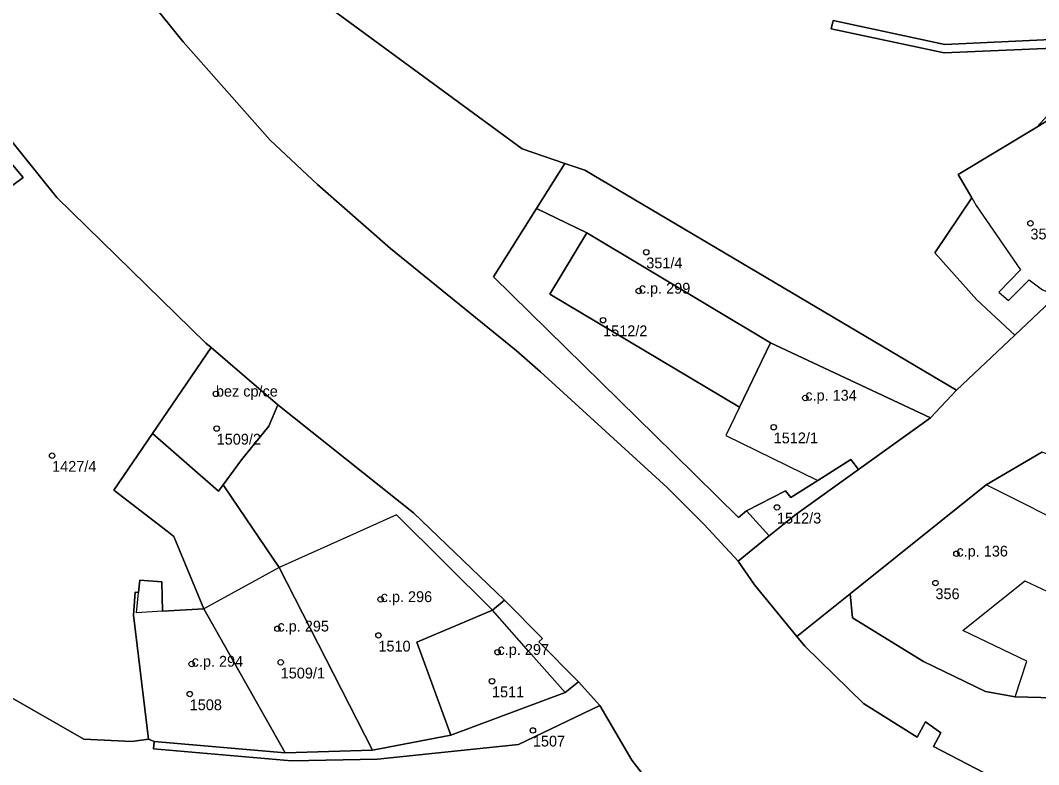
# Model space of a CAD drawing. Extents: x -878211 to -870363, y -1058464 to -1052522.
# Drawn here: x -874764.7 to -874670.5, y -1056238.3 to -1056169.5 of the extents above; entities that cross this region are included whole.
import ezdxf

# ---------------------------------------------------------------- set-up
doc = ezdxf.new("R2010")
doc.units = 0
for name, color, linetype in [('Definiční body', 7, 'Continuous'), ('Polygon budovy', 7, 'Continuous'), ('Polygon parcely', 7, 'Continuous')]:
    doc.layers.add(name, color=color, linetype=linetype)

msp = doc.modelspace()

# ---------------------------------------------------------------- linework, layer by layer
at = {"layer": 'Definiční body'}
for centre in [(-874671.3, -1056188.27994), (-874706.81, -1056190.94994), (-874707.5, -1056194.52994), (-874710.8, -1056197.22994), (-874746.59, -1056204.03994), (-874692.11, -1056204.41994), (-874746.52, -1056207.23994), (-874695.03, -1056207.11994), (-874761.73, -1056209.74994), (-874694.73, -1056214.52994), (-874678.14, -1056218.81994), (-874680.08, -1056221.51994), (-874731.36, -1056223.02994), (-874740.9, -1056225.74994), (-874731.57, -1056226.35994), (-874720.56, -1056227.90994), (-874748.83, -1056228.99994), (-874740.6, -1056228.84994), (-874721.07, -1056230.58994), (-874749.01, -1056231.77994), (-874717.29, -1056235.13994)]:
    msp.add_circle(centre, 0.25, dxfattribs=at)
at = {"layer": 'Polygon budovy'}
for points in [[(-874677.98, -1056183.76), (-874676.72, -1056185.93), (-874676.32, -1056186.62), (-874672.23, -1056192.57), (-874674.22, -1056194.63), (-874673.33, -1056195.4), (-874671.43, -1056193.49), (-874670.18, -1056194.41), (-874668.85, -1056194.96), (-874667.89, -1056195.41), (-874666.98, -1056194.26), (-874667.6, -1056193.93), (-874661.14, -1056188.51), (-874667.82, -1056178.48), (-874668.25, -1056177.84), (-874670.71, -1056179.4)], [(-874712.31, -1056189.17), (-874715.72, -1056194.83), (-874698.19, -1056205.27), (-874695.34, -1056199.31)], [(-874752.45, -1056207.7), (-874746.34, -1056213.03), (-874745.91, -1056212.45), (-874744.24, -1056210.15), (-874741.71, -1056207.02), (-874740.87, -1056205.06), (-874747.04, -1056199.75)], [(-874699.45, -1056207.9), (-874690.94, -1056212.04), (-874687.9, -1056210.09), (-874687.2, -1056211.04), (-874680.55, -1056206.24), (-874695.34, -1056199.31), (-874698.19, -1056205.27)], [(-874675.38, -1056212.44), (-874687.96, -1056222.51), (-874687.74, -1056224.74), (-874681.17, -1056228.78), (-874675.44, -1056231.54), (-874672.71, -1056232.05), (-874671.64, -1056228.75), (-874677.55, -1056225.92), (-874671.81, -1056221.33), (-874669.72, -1056222.29), (-874666.44, -1056216.93)], [(-874728.01, -1056226.99), (-874721.01, -1056224.03), (-874729.9, -1056215.22), (-874734.21, -1056217.16), (-874740.73, -1056220.09), (-874732.13, -1056236.97), (-874724.86, -1056235.58)], [(-874747.71, -1056223.89), (-874740.2, -1056237.21), (-874732.13, -1056236.97), (-874740.73, -1056220.09)], [(-874754.04, -1056222.36), (-874754.2, -1056224.49), (-874752.81, -1056235.95), (-874752.29, -1056236.15), (-874740.2, -1056237.21), (-874747.71, -1056223.89), (-874751.53, -1056224.13), (-874753.92, -1056224.28), (-874753.74, -1056222.39)], [(-874721.01, -1056224.03), (-874728.01, -1056226.99), (-874724.86, -1056235.58), (-874714.32, -1056231.63), (-874717.67, -1056227.86)]]:
    msp.add_lwpolyline(points, close=True, dxfattribs=at)
at = {"layer": 'Polygon parcely'}
for points in [[(-874779.01, -1056127.66), (-874780.45, -1056125.66), (-874793.17, -1056142.82), (-874792.46, -1056145.61), (-874788.37, -1056151.02), (-874786.78, -1056152.78), (-874770.12, -1056174.96), (-874761.29, -1056185.88), (-874747.51, -1056199.34), (-874747.04, -1056199.75), (-874740.87, -1056205.06), (-874728.32, -1056215.02), (-874719.92, -1056223.09), (-874716.4, -1056226.65), (-874716.73, -1056226.96), (-874713.06, -1056230.64), (-874711.1, -1056232.84), (-874708.16, -1056237.89), (-874707.28, -1056238.99), (-874703.07, -1056243.11), (-874695.31, -1056252.07), (-874686.26, -1056258.1), (-874668.18, -1056265.93)], [(-874755.19, -1056164.59), (-874749.63, -1056171.52), (-874741.58, -1056180.59), (-874737.21, -1056184.7), (-874730.46, -1056190.6), (-874718.85, -1056200.03), (-874716.6, -1056202), (-874704.89, -1056212.69), (-874701.45, -1056216.12), (-874698.33, -1056219.5), (-874695.44, -1056217.17), (-874697.54, -1056214.84), (-874698.28, -1056215.45), (-874704.29, -1056209.55), (-874720.93, -1056193.21), (-874716.96, -1056186.91), (-874714.34, -1056182.75), (-874718.29, -1056181.41), (-874745.51, -1056161.39)], [(-874745.51, -1056161.39), (-874718.29, -1056181.41), (-874714.34, -1056182.75), (-874712.49, -1056183.37), (-874678.15, -1056203.7), (-874672.74, -1056198.62), (-874676.24, -1056195.34), (-874680.13, -1056191), (-874676.72, -1056185.93), (-874677.98, -1056183.76), (-874670.71, -1056179.4), (-874668.7, -1056177.22)], [(-874664.15, -1056243.93), (-874672.49, -1056240.67), (-874680.25, -1056236.62), (-874679.58, -1056235.37), (-874681, -1056234.34), (-874681.77, -1056235.77), (-874686.72, -1056232.64), (-874692.16, -1056227.35), (-874692.89, -1056226.46), (-874696.8, -1056221.69), (-874698.33, -1056219.5), (-874701.45, -1056216.12), (-874704.89, -1056212.69), (-874716.6, -1056202), (-874718.85, -1056200.03), (-874730.46, -1056190.6), (-874737.21, -1056184.7), (-874741.58, -1056180.59), (-874749.63, -1056171.52), (-874755.19, -1056164.59)], [(-874669.43, -1056171.29), (-874679.22, -1056171.74), (-874689.55, -1056169.54), (-874689.71, -1056170.32), (-874679.26, -1056172.52), (-874669.23, -1056172.08)], [(-874669.23, -1056172.08), (-874679.26, -1056172.52), (-874689.71, -1056170.32), (-874689.55, -1056169.54), (-874679.22, -1056171.74), (-874669.43, -1056171.29)], [(-874774.8, -1056226.8), (-874758.8, -1056235.95), (-874754.35, -1056236.17), (-874752.81, -1056235.95), (-874754.2, -1056224.49), (-874754.04, -1056222.36), (-874753.74, -1056222.39), (-874753.63, -1056221.26), (-874751.58, -1056221.41), (-874751.53, -1056224.13), (-874747.71, -1056223.89), (-874750.48, -1056217.21), (-874751.09, -1056216.74), (-874756.02, -1056212.93), (-874752.45, -1056207.7), (-874747.04, -1056199.75), (-874747.51, -1056199.34), (-874761.29, -1056185.88), (-874770.12, -1056174.96)], [(-874769.55, -1056177.94), (-874764.4, -1056184.06), (-874768.14, -1056186.8)], [(-874668.85, -1056194.96), (-874672.74, -1056198.62), (-874678.15, -1056203.7), (-874680.55, -1056206.24), (-874687.2, -1056211.04), (-874692.98, -1056215.18), (-874695.44, -1056217.17), (-874698.33, -1056219.5), (-874696.8, -1056221.69), (-874692.89, -1056226.46), (-874687.96, -1056222.51), (-874675.38, -1056212.44), (-874670.25, -1056209.43)], [(-874666.81, -1056232.19), (-874672.71, -1056232.05), (-874675.44, -1056231.54), (-874681.17, -1056228.78), (-874687.74, -1056224.74), (-874687.96, -1056222.51), (-874692.89, -1056226.46), (-874692.16, -1056227.35), (-874686.72, -1056232.64), (-874681.77, -1056235.77), (-874681, -1056234.34), (-874679.58, -1056235.37), (-874680.25, -1056236.62), (-874672.49, -1056240.67), (-874664.15, -1056243.93)], [(-874773.13, -1056237.53), (-874759.69, -1056240.67), (-874729.27, -1056243.94), (-874710.36, -1056243.35), (-874703.07, -1056243.11), (-874707.28, -1056238.99), (-874708.16, -1056237.89), (-874711.1, -1056232.84), (-874718.62, -1056236.45), (-874731.64, -1056237.78), (-874739.6, -1056237.96), (-874752.36, -1056236.83), (-874752.29, -1056236.15), (-874752.81, -1056235.95), (-874754.35, -1056236.17), (-874758.8, -1056235.95), (-874774.8, -1056226.8)]]:
    msp.add_lwpolyline(points, dxfattribs=at)
for points in [[(-874768.14, -1056186.8), (-874764.4, -1056184.06), (-874769.55, -1056177.94), (-874773.8, -1056173.53), (-874778.66, -1056169.8), (-874783.43, -1056165.72), (-874785.6, -1056163.06), (-874790.16, -1056157.06), (-874792.97, -1056160.86), (-874789.38, -1056164.87), (-874788.09, -1056167.27), (-874786.56, -1056169.13), (-874784.51, -1056170.94), (-874777.23, -1056176.57), (-874773.7, -1056180.1)], [(-874668.25, -1056177.84), (-874668.7, -1056177.22), (-874670.71, -1056179.4)], [(-874668.85, -1056194.96), (-874667.89, -1056195.41), (-874666.98, -1056194.26), (-874667.6, -1056193.93), (-874661.14, -1056188.51), (-874659.94, -1056187.5), (-874667.82, -1056178.48), (-874668.25, -1056177.84), (-874670.71, -1056179.4), (-874677.98, -1056183.76), (-874676.72, -1056185.93), (-874680.13, -1056191), (-874676.24, -1056195.34), (-874672.74, -1056198.62)], [(-874695.34, -1056199.31), (-874680.55, -1056206.24), (-874678.15, -1056203.7), (-874712.49, -1056183.37), (-874714.34, -1056182.75), (-874716.96, -1056186.91), (-874712.31, -1056189.17)], [(-874680.55, -1056206.24), (-874695.34, -1056199.31), (-874698.19, -1056205.27), (-874715.72, -1056194.83), (-874712.31, -1056189.17), (-874716.96, -1056186.91), (-874720.93, -1056193.21), (-874704.29, -1056209.55), (-874698.28, -1056215.45), (-874697.54, -1056214.84), (-874693.93, -1056213), (-874693.45, -1056213.62), (-874690.94, -1056212.04), (-874687.9, -1056210.09), (-874687.2, -1056211.04)], [(-874712.31, -1056189.17), (-874715.72, -1056194.83), (-874698.19, -1056205.27), (-874695.34, -1056199.31)], [(-874747.04, -1056199.75), (-874752.45, -1056207.7), (-874746.34, -1056213.03), (-874745.91, -1056212.45), (-874744.24, -1056210.15), (-874741.71, -1056207.02), (-874740.87, -1056205.06)], [(-874724.86, -1056235.58), (-874728.01, -1056226.99), (-874721.01, -1056224.03), (-874719.92, -1056223.09), (-874728.32, -1056215.02), (-874740.87, -1056205.06), (-874741.71, -1056207.02), (-874744.24, -1056210.15), (-874745.91, -1056212.45), (-874745.08, -1056213.67), (-874740.73, -1056220.09), (-874732.13, -1056236.97)], [(-874745.91, -1056212.45), (-874746.34, -1056213.03), (-874752.45, -1056207.7), (-874756.02, -1056212.93), (-874751.09, -1056216.74), (-874750.48, -1056217.21), (-874747.71, -1056223.89), (-874740.2, -1056237.21), (-874732.13, -1056236.97), (-874740.73, -1056220.09), (-874745.08, -1056213.67)], [(-874672.71, -1056232.05), (-874666.81, -1056232.19), (-874666.17, -1056230.46), (-874661.58, -1056218.05), (-874659.58, -1056213.18), (-874670.25, -1056209.43), (-874675.38, -1056212.44), (-874687.96, -1056222.51), (-874687.74, -1056224.74), (-874681.17, -1056228.78), (-874675.44, -1056231.54)], [(-874692.98, -1056215.18), (-874687.2, -1056211.04), (-874687.9, -1056210.09), (-874690.94, -1056212.04), (-874693.45, -1056213.62), (-874693.93, -1056213), (-874697.54, -1056214.84), (-874695.44, -1056217.17)], [(-874740.2, -1056237.21), (-874747.71, -1056223.89), (-874751.53, -1056224.13), (-874751.58, -1056221.41), (-874753.63, -1056221.26), (-874753.74, -1056222.39), (-874754.04, -1056222.36), (-874754.2, -1056224.49), (-874752.81, -1056235.95), (-874752.29, -1056236.15)], [(-874724.86, -1056235.58), (-874714.32, -1056231.63), (-874713.06, -1056230.64), (-874716.73, -1056226.96), (-874716.4, -1056226.65), (-874719.92, -1056223.09), (-874721.01, -1056224.03), (-874728.01, -1056226.99)], [(-874724.86, -1056235.58), (-874732.13, -1056236.97), (-874740.2, -1056237.21), (-874752.29, -1056236.15), (-874752.36, -1056236.83), (-874739.6, -1056237.96), (-874731.64, -1056237.78), (-874718.62, -1056236.45), (-874711.1, -1056232.84), (-874713.06, -1056230.64), (-874714.32, -1056231.63)]]:
    msp.add_lwpolyline(points, close=True, dxfattribs=at)

# ---------------------------------------------------------------- texts
at = {"layer": 'Definiční body'}
for s, p in [('350/1', (-874671.3, -1056189.769)), ('351/4', (-874706.81, -1056192.439)), ('c.p. 299', (-874707.5, -1056194.78)), ('1512/2', (-874710.8, -1056198.719)), ('bez cp/ce', (-874746.59, -1056204.29)), ('c.p. 134', (-874692.11, -1056204.669)), ('1512/1', (-874695.03, -1056208.609)), ('1509/2', (-874746.52, -1056208.729)), ('1427/4', (-874761.73, -1056211.239)), ('1512/3', (-874694.73, -1056216.019)), ('c.p. 136', (-874678.14, -1056219.07)), ('c.p. 296', (-874731.36, -1056223.28)), ('356', (-874680.08, -1056223.009)), ('c.p. 295', (-874740.9, -1056226)), ('1510', (-874731.57, -1056227.849)), ('c.p. 297', (-874720.56, -1056228.159)), ('c.p. 294', (-874748.83, -1056229.25)), ('1509/1', (-874740.6, -1056230.339)), ('1511', (-874721.07, -1056232.079)), ('1508', (-874749.01, -1056233.269)), ('1507', (-874717.29, -1056236.629))]:
    msp.add_text(s, height=0.999996, dxfattribs=at).set_placement(p)

doc.saveas('drawing.dxf')
